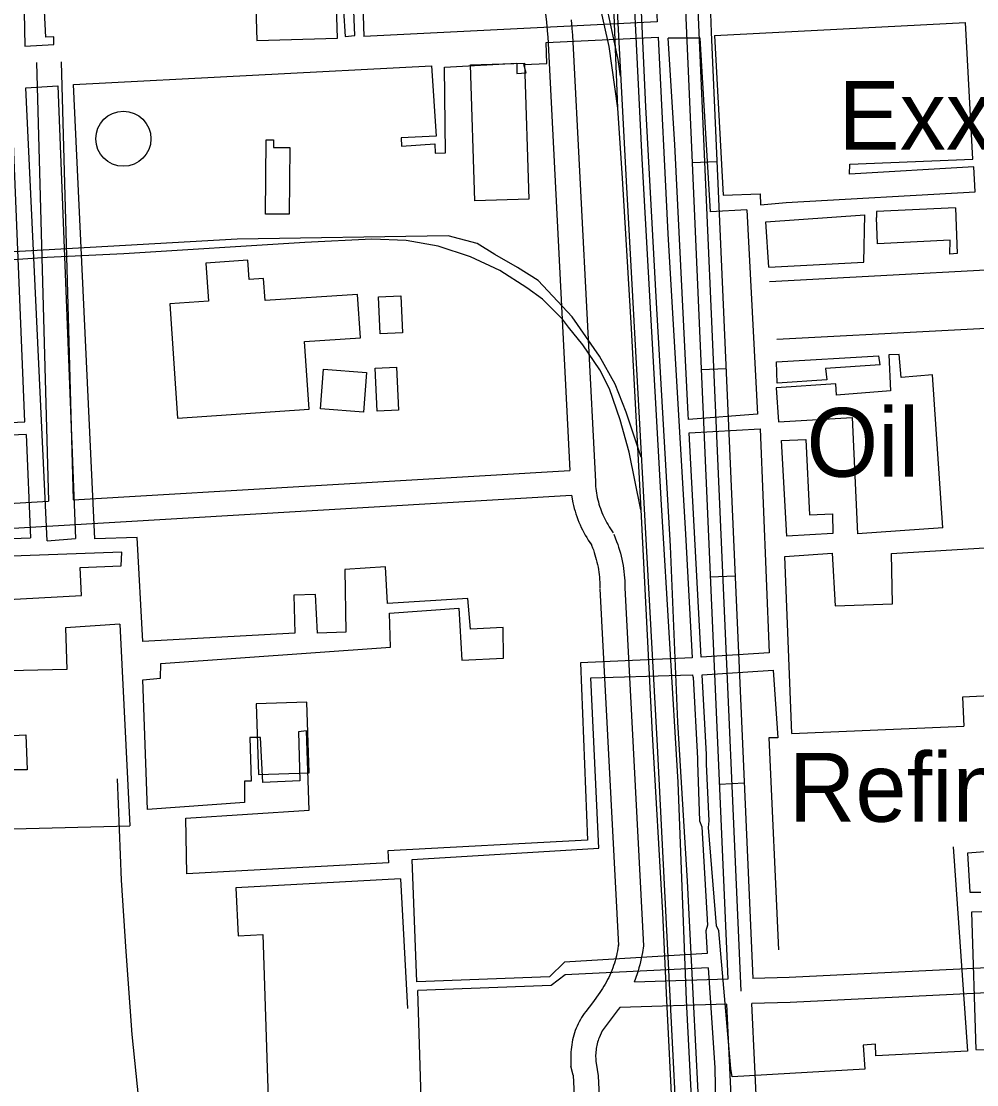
# Model space of a CAD drawing. Extents: x 3313447 to 3351316, y 703786 to 729172.
# Drawn here: x 3329508 to 3330659, y 721489 to 722771 of the extents above; entities that cross this region are included whole.
import ezdxf

# ---------------------------------------------------------------- set-up
doc = ezdxf.new("R2010")
doc.units = 0
for name, color, linetype in [('V-BLDG-IDEN', 7, 'Continuous'), ('V-BLDG-OTLN', 7, 'Continuous'), ('V-DOMW-TANK', 7, 'Continuous'), ('V-RAIL-TRAK', 7, 'Continuous'), ('V-ROAD-CNTR', 7, 'Continuous'), ('V-UTIL-LINE', 7, 'Continuous')]:
    doc.layers.add(name, color=color, linetype=linetype)

msp = doc.modelspace()

# ---------------------------------------------------------------- linework, layer by layer
at = {"layer": 'V-BLDG-OTLN'}
for points in [[(3330113.9, 722720.9), (3330119.2, 722556.9), (3330054.2, 722554.8), (3330048.9, 722718.8)], [(3329831.4, 722619.1), (3329830.7, 722538.7), (3329801.9, 722538.9), (3329802.7, 722628.4), (3329811.9, 722628.3), (3329811.9, 722619.2)], [(3329696.2, 722293), (3329854.5, 722303.6), (3329849, 722385.3), (3329916.4, 722389.8), (3329912.9, 722442), (3329801.6, 722434.5), (3329799.8, 722461.2), (3329782.6, 722460.1), (3329781, 722483.1), (3329730.4, 722479.7), (3329733.5, 722434), (3329687, 722430.8)], [(3329940.3, 722394.6), (3329938.3, 722439), (3329965.3, 722440.2), (3329967.3, 722395.8)], [(3329920.3, 722300.2), (3329868.5, 722303.9), (3329872, 722351.7), (3329923.7, 722348)], [(3329959.7, 722354.2), (3329962.3, 722302.5), (3329936.7, 722301.2), (3329934.1, 722352.9)], [(3329854.6, 721865.3), (3329851.9, 721950.4), (3329791, 721948.5), (3329793.7, 721863.3)]]:
    msp.add_lwpolyline(points, close=True, dxfattribs=at)
at = {"layer": 'V-DOMW-TANK'}
msp.add_circle((3329630.9, 722629.6), 33.2, dxfattribs=at)
at = {"layer": 'V-RAIL-TRAK'}
for points in [[(3330131.5, 724591.3), (3330139.3, 724420.3), (3330148.6, 724227.2), (3330159, 724024.7), (3330170.2, 723797.3), (3330181.3, 723583), (3330191.8, 723354.2), (3330204.1, 723119.5), (3330215.1, 722932.3), (3330219.8, 722830.3), (3330226.1, 722666.6)], [(3330326, 721424.9), (3330317.7, 721591.3), (3330310.5, 721734.5), (3330298.8, 721926.5), (3330289.8, 722138.4), (3330273, 722431.7), (3330260.4, 722668.1), (3330249.5, 722907), (3330231, 723213.3), (3330218.2, 723465.7), (3330204, 723743), (3330189.9, 724004.8), (3330176.5, 724253), (3330165.3, 724472.1), (3330161.1, 724586)], [(3330202.9, 722798.6), (3330215.6, 722740.7), (3330226.1, 722666.6), (3330231.7, 722582), (3330242.7, 722401), (3330254.2, 722182.2), (3330268, 721911.8), (3330280.2, 721696.5), (3330285.2, 721591.3), (3330291.8, 721453.8)], [(3330254.2, 722182.2), (3330240, 722251.9), (3330229.4, 722291), (3330216.3, 722328), (3330204.8, 722351.2), (3330184.5, 722381.3), (3330167.1, 722402.6), (3330159.7, 722412), (3330135.7, 722436.2), (3330116.9, 722450), (3330084.5, 722471), (3330049.1, 722487.4), (3330010.2, 722500.1), (3329971.6, 722506.8), (3329930, 722508.7), (3329849.6, 722504.5), (3329631.5, 722490.9), (3329538.9, 722486.4), (3329498, 722483.6), (3329390.2, 722477.2), (3329212, 722469), (3329084.7, 722462.8)]]:
    msp.add_lwpolyline(points, dxfattribs=at)
at = {"layer": 'V-ROAD-CNTR'}
for p, q in [((3330345.9, 722602), (3330315.9, 722600.7)), ((3330356.9, 722352.3), (3330326.9, 722351)), ((3330367.8, 722102.5), (3330337.9, 722101.2)), ((3330378.8, 721852.8), (3330348.8, 721851.4))]:
    msp.add_line(p, q, dxfattribs=at)
for points in [[(3330000.9, 727371.9), (3330011.6, 727012.1), (3330035.2, 726652.6), (3330064.9, 725878.2), (3330103.9, 725200.1), (3330125.1, 724765.2), (3330141.9, 724403.2), (3330158.8, 724097.3), (3330186.3, 723532.1), (3330236.4, 722578.7), (3330273.8, 721897.8), (3330314.5, 721094.9), (3330366.7, 720143), (3330425.8, 719049.4), (3330444.1, 718741)], [(3330466.9, 718738.2), (3330443.3, 719091.6), (3330425.1, 719389.4), (3330397.6, 719905.3), (3330375.8, 720281.9), (3330354.7, 720674.1), (3330332.4, 721137.8), (3330309.1, 721591.1), (3330299.2, 721854.1), (3330279.3, 722188.2), (3330255.7, 722605.3), (3330239.5, 722940.1), (3330206.8, 723536.2), (3330170.6, 724242), (3330145.9, 724754), (3330120.4, 725277), (3330081.8, 725930.6), (3330062.3, 726434.2), (3330049.6, 726666.1), (3330008.6, 727333.2), (3330005.4, 727371.9)], [(3330229.8, 722705), (3330226.8, 722725.1), (3330206.5, 722821.4), (3330186.6, 722875.1), (3330169.7, 722917.9), (3330137.7, 722976.9), (3330112.5, 723021.9), (3330083.6, 723061.2), (3330048.7, 723102.7), (3330000, 723151.4), (3329959.9, 723189.8), (3329906.5, 723223.6), (3329849.9, 723262.2), (3329775.5, 723299.1), (3329670.5, 723334.7), (3329586.2, 723351.8), (3329525.3, 723358.9), (3329412.1, 723359.9)], [(3330311.5, 723140.7), (3330302.4, 723128.7), (3330294.3, 723103.6), (3330309.1, 722757), (3330359.2, 721616.4)], [(3330309.4, 723101.6), (3330324, 722757.6), (3330374.8, 721601.9)], [(3330337.6, 722791.8), (3330339, 722758.3), (3330389.2, 721617.3)], [(3330139.3, 722780.4), (3330140.4, 722770.2), (3330141.3, 722760), (3330142, 722751.9)], [(3330170.2, 722773.1), (3330171.2, 722762.6), (3330171.9, 722754.5)], [(3330142, 722752.4), (3330168.8, 722229.7)], [(3330171.9, 722754), (3330199.5, 722216.4)], [(3329526.1, 722721.7), (3329540.5, 722192.6)], [(3329556.1, 722722.5), (3329570.5, 722194.4)], [(3330254.7, 722245.8), (3330236.7, 722300.1), (3330223.3, 722333.7), (3330204.4, 722367.5), (3330171.3, 722414.8), (3330130.4, 722458.7), (3330105.5, 722474.4), (3330078.5, 722490.1), (3330057.1, 722503.3), (3330022.3, 722512.8), (3329768, 722508.7), (3329300.1, 722482.1), (3329056.2, 722463.5)], [(3329570.5, 722194.4), (3330168.8, 722229.7)], [(3330199.5, 722216.2), (3330199.7, 722213.3), (3330199.8, 722210.6), (3330200.1, 722207.9), (3330200.4, 722205.2), (3330200.8, 722202.5), (3330201.3, 722199.8), (3330201.8, 722197.1), (3330202.4, 722194.5), (3330203.1, 722191.8), (3330203.8, 722189.2), (3330204.6, 722186.6), (3330205.5, 722184), (3330206.4, 722181.4), (3330207.4, 722178.9), (3330208.5, 722176.4), (3330209.6, 722173.9), (3330210.8, 722171.5), (3330212, 722169), (3330213.4, 722166.6), (3330214.7, 722164.3), (3330216.2, 722162), (3330220.9, 722154.7)], [(3328790.8, 722148.4), (3329540.5, 722192.6)], [(3329226.1, 722144), (3330170.7, 722199.8)], [(3330170.7, 722199.8), (3330172.4, 722190.9), (3330173.2, 722187.5), (3330174.1, 722184.1), (3330175, 722180.7), (3330176, 722177.4), (3330177.1, 722174.1), (3330178.3, 722170.8), (3330179.6, 722167.5), (3330181, 722164.3), (3330182.4, 722161.1), (3330184, 722158), (3330185.6, 722154.9), (3330187.3, 722151.8), (3330189, 722148.8), (3330190.9, 722145.8), (3330192.8, 722142.9), (3330194.7, 722140.1), (3330195, 722139.8)], [(3330221.8, 722152.9), (3330225.1, 722144.3), (3330226.4, 722140.7), (3330227.5, 722137.2), (3330228.6, 722133.6), (3330229.6, 722130), (3330230.6, 722126.3), (3330231.4, 722122.7), (3330232.1, 722119), (3330232.8, 722115.3), (3330233.4, 722111.6), (3330233.9, 722107.8), (3330234.3, 722104.1), (3330234.6, 722100.4), (3330234.8, 722096.6), (3330234.9, 722092.9), (3330235, 722089.2), (3330235, 722087.6)], [(3330193.4, 722142.5), (3330194.7, 722139.6), (3330195.9, 722136.7), (3330197, 722133.9), (3330198, 722131), (3330198.9, 722128.1), (3330199.8, 722125.2), (3330200.6, 722122.3), (3330201.4, 722119.3), (3330202.1, 722116.3), (3330202.7, 722113.3), (3330203.2, 722110.3), (3330203.7, 722107.3), (3330204.1, 722104.3), (3330204.4, 722101.3), (3330204.6, 722098.2), (3330204.8, 722095.2), (3330204.9, 722092.1), (3330205, 722089), (3330205, 722087.7)], [(3330205, 722086.9), (3330227.4, 721657.1)], [(3330234.9, 722088.4), (3330257.5, 721656.7)], [(3329623.3, 721857.9), (3329628.4, 721735.9), (3329634, 721650), (3329641, 721549.9), (3329650.8, 721455.7), (3329657, 721369.5), (3329664.8, 721286.5), (3329666.1, 721220.5), (3329668.7, 721162.2), (3329668.2, 721127.2), (3329562.6, 721122.8), (3329434.6, 721118.6), (3329349, 721114.9), (3329279.5, 721113)], [(3330227.5, 721659.9), (3330227.1, 721656.6), (3330226.6, 721653.6), (3330226.1, 721650.6), (3330225.5, 721647.6), (3330224.8, 721644.6), (3330224, 721641.7), (3330223.2, 721638.7), (3330222.3, 721635.8), (3330221.3, 721632.9), (3330220.3, 721630), (3330219.2, 721627.1), (3330218.1, 721624.3), (3330216.8, 721621.5), (3330215.5, 721618.7), (3330214.2, 721616), (3330212.8, 721613.3), (3330211.3, 721610.6), (3330209.7, 721608), (3330208.1, 721605.4), (3330206.5, 721602.8), (3330204.7, 721600.3), (3330195.8, 721587.9)], [(3330257.5, 721656.7), (3330256.2, 721648.7), (3330255.5, 721644.9), (3330254.8, 721641.3), (3330253.9, 721637.6), (3330253, 721633.9), (3330252, 721630.3), (3330250.9, 721626.7), (3330249.7, 721623.1), (3330246.1, 721613.1)], [(3331759.7, 721653.7), (3330434, 721588.6), (3330388, 721587.2)], [(3330836.1, 721638.4), (3330432.8, 721618.6), (3330389.2, 721617.3)], [(3330359.2, 721616.4), (3330246.4, 721613.1)], [(3330195.8, 721587.9), (3330187.8, 721577.6), (3330186.1, 721575.3), (3330184.5, 721572.8), (3330182.9, 721570.4), (3330181.4, 721567.8), (3330180, 721565.2), (3330178.7, 721562.6), (3330177.5, 721560), (3330176.3, 721557.3), (3330175.3, 721554.5), (3330174.3, 721551.7), (3330173.4, 721548.9), (3330172.7, 721546.1), (3330172, 721543.2), (3330171.4, 721540.4), (3330170.9, 721537.5), (3330170.5, 721534.6), (3330170.2, 721531.7), (3330169.9, 721528.7), (3330169.8, 721525.8), (3330169.7, 721511.6)], [(3330358, 721586.4), (3330228.9, 721582.5)], [(3330365.1, 721433.2), (3330358, 721586.4)], [(3330431.7, 720793.9), (3330395.1, 721434.7), (3330388, 721587.2)], [(3330228.9, 721582.5), (3330227.1, 721580), (3330207.6, 721554.2)], [(3330207.6, 721554.2), (3330204.1, 721546), (3330203.4, 721544.2), (3330202.8, 721542.4), (3330202.2, 721540.5), (3330201.7, 721538.6), (3330201.2, 721536.7), (3330200.9, 721534.8), (3330200.5, 721532.9), (3330200.3, 721530.9), (3330200, 721529), (3330199.9, 721527), (3330199.8, 721525.1), (3330199.8, 721523.1), (3330199.9, 721521.2), (3330200, 721519.2), (3330200.2, 721517.3), (3330200.4, 721515.3), (3330202.8, 721499.9)], [(3330172.7, 721500.9), (3330169.7, 721511.6)], [(3330172.7, 721500.9), (3330188.7, 721176.5)], [(3330202.8, 721499.9), (3330218.7, 721178)]]:
    msp.add_lwpolyline(points, dxfattribs=at)
at = {"layer": 'V-UTIL-LINE'}
for p, q in [((3330274, 722770.6), (3329920.4, 722752.8)), ((3330342.9, 722754.1), (3330645.4, 722769.6)), ((3330140, 722745.7), (3330275, 722752.3)), ((3330381.9, 722543.9), (3330394.6, 722297.5)), ((3330542.5, 722357.2), (3330541, 722367.9)), ((3330394.6, 722297.5), (3330311.7, 722291.2)), ((3329513.6, 722273), (3329519.1, 722148.7)), ((3330327, 722004.6), (3330312.5, 722275.3)), ((3330485.2, 722177.6), (3330485.3, 722153.7)), ((3330617.9, 722160.6), (3330515.1, 722153.5)), ((3329539.2, 722145), (3329573.1, 722147.6)), ((3329628.3, 722114.7), (3329628.9, 722131.3)), ((3329626.6, 722044.4), (3329638.6, 721801.4)), ((3330302, 721983.1), (3330316.9, 721983.5)), ((3330317.1, 721980.7), (3330316.9, 721983.5)), ((3330436.3, 721912.5), (3330643.3, 721921.5)), ((3329964.6, 721737.3), (3329973.1, 721581.3)), ((3330007.5, 720934), (3329985.4, 721602.8))]:
    msp.add_line(p, q, dxfattribs=at)
for points in [[(3330184.7, 724503.2), (3330185.3, 724490.2), (3330191.3, 724387.6), (3330230.5, 724261.8), (3330234.7, 724258.4), (3330237.5, 724237.1), (3330199.2, 724194.9), (3330218, 723872.7), (3330240.2, 723443.9), (3330270, 722851.2), (3330274, 722770.6)], [(3329912.1, 723021.8), (3329920.4, 722752.8)], [(3329894.1, 722816), (3329897.9, 722753), (3329909.7, 722754.1), (3329899, 723020.7)], [(3329785.8, 722947), (3329791.7, 722748), (3329888.9, 722750.9), (3329887.7, 722789)], [(3329511.4, 722782.2), (3329512, 722741.4), (3329547.3, 722743.3), (3329547.2, 722752.7), (3329537.5, 722752.3), (3329536, 722783.4)], [(3330342.9, 722754.1), (3330353.2, 722561.5), (3330398.1, 722563.4), (3330398.2, 722549.8), (3330429.1, 722552.8), (3330656.8, 722565.6), (3330655.4, 722595.6), (3330505.7, 722586.8), (3330505.9, 722599), (3330654.2, 722604.9), (3330645.4, 722769.6)], [(3330275, 722752.3), (3330286.8, 722515.2), (3330307.9, 722153.1), (3330315.9, 722003.7)], [(3330315.9, 722003.7), (3330181.5, 721997.7), (3330190.1, 721784.2), (3329949.6, 721771.2), (3329950.4, 721756.7), (3329707.4, 721743.7), (3329706, 721810.5), (3329854.5, 721820.2), (3329851.6, 721915.8), (3329841.9, 721914.7), (3329843.6, 721855.8), (3329798.9, 721853.5), (3329796.2, 721907.9), (3329783.4, 721907.8), (3329784.7, 721855.2), (3329776.8, 721855.1), (3329776.9, 721829.5), (3329659.9, 721821), (3329654.3, 721977.4), (3329675.7, 721979.3), (3329676, 721996.9), (3329952.5, 722016.7), (3329951.3, 722057.9), (3330035, 722063.8), (3330038.5, 722001.2), (3330088.6, 722003.5), (3330088.5, 722040.5), (3330049, 722038.6), (3330046, 722075.3), (3329949.1, 722069.3), (3329946.8, 722113.6), (3329897.7, 722110.2), (3329898.8, 722034.7), (3329864.8, 722033.5), (3329862.5, 722080.3), (3329836.2, 722079.4), (3329837.5, 722033.7), (3329654.4, 722023.5), (3329647.5, 722148.8), (3329596.7, 722147.5), (3329571, 722695), (3330002, 722717.6), (3330007.6, 722632.8), (3329965.7, 722630.9), (3329966.1, 722620.9), (3330006.2, 722623.5), (3330006.3, 722612.4), (3330019.1, 722612.8), (3330017.9, 722716), (3330104.8, 722720.6), (3330104.8, 722708.5), (3330115.9, 722709.2), (3330113.4, 722719.2), (3330141.1, 722720.4), (3330140, 722745.7)], [(3330381.9, 722543.9), (3330338, 722541.6), (3330325.8, 722751), (3330287.1, 722750.9)], [(3330311.7, 722291.2), (3330311.3, 722297.8), (3330295.2, 722622.7), (3330287.1, 722750.9)], [(3329539.2, 722145), (3329513.3, 722691.2), (3329552, 722693.5), (3329573.1, 722147.6)], [(3329476.9, 722286.7), (3329512.2, 722288.2), (3329496, 722682.8)], [(3330408.3, 722474.9), (3330404.8, 722529.6), (3330523.9, 722537.8)], [(3330408.3, 722474.9), (3330522.8, 722481), (3330523.9, 722537.8)], [(3330633.3, 722546.3), (3330538.1, 722542), (3330538.1, 722534.8)], [(3330633.3, 722546.3), (3330635.3, 722491.3), (3330626.6, 722490.5), (3330626.9, 722507.5), (3330539.3, 722502.9), (3330538.1, 722534.8)], [(3330418, 722388.1), (3330815.4, 722408.8), (3330811.2, 722479), (3330409.4, 722457.3)], [(3330617.9, 722160.6), (3330605.5, 722345), (3330567.8, 722341.7), (3330565.3, 722369.4), (3330553.1, 722369), (3330555.1, 722325.7), (3330490, 722320.6), (3330489.3, 722334.4), (3330417.3, 722329.5), (3330419.9, 722288.4), (3330508.9, 722293.7), (3330515.1, 722153.5)], [(3330542.5, 722357.2), (3330476.7, 722352.7), (3330478.2, 722338.9), (3330418.6, 722335.1), (3330417.5, 722360.7), (3330541, 722367.9)], [(3330312.5, 722275.3), (3330398.1, 722279.9), (3330408.8, 722009.9), (3330327, 722004.6)], [(3329513.6, 722273), (3329476.2, 722271.4), (3329478.2, 722225.4), (3329463.7, 722223.6), (3329460, 722269.3), (3329312.2, 722261.2), (3329313.3, 722241.2), (3329250, 722236.7), (3329250.8, 722139.1), (3329519.1, 722148.7)], [(3330485.3, 722153.7), (3330429.9, 722150.6), (3330423.8, 722265.9), (3330452.9, 722267.1), (3330457.2, 722176.4), (3330485.2, 722177.6)], [(3330436.3, 721912.5), (3330427.6, 722126), (3330484.8, 722130.1), (3330488.2, 722066.4), (3330557.4, 722068.9), (3330556.1, 722129.8), (3330780.7, 722143.4)], [(3329628.9, 722131.3), (3329253.4, 722117.6), (3329257.6, 722025.9), (3329328.9, 722028.3), (3329328.8, 722062.3), (3329309.4, 722061.8), (3329307.9, 722077.4), (3329368.8, 722079.4), (3329367.7, 722106.4), (3329390.9, 722108.3), (3329393.4, 722076.4), (3329446.7, 722078.4), (3329444.9, 722108.5), (3329475.3, 722109.7), (3329477.2, 722073.4), (3329580.4, 722079.1), (3329578.8, 722112.7), (3329628.3, 722114.7)], [(3329626.6, 722044.4), (3329561.2, 722040.2), (3329562.8, 721989.7), (3329370.4, 721985.3), (3329368, 722046.9), (3329343.7, 722046.4), (3329345.6, 722020.1), (3329259.1, 722016.2), (3329268.9, 721788.1), (3329391.1, 721794.6), (3329388.4, 721843.8), (3329358.3, 721841.5), (3329359.1, 721817.7), (3329323.1, 721813.3), (3329322.5, 721861.8), (3329350.9, 721864.3), (3329349.7, 721903.1), (3329513.4, 721911.2), (3329515, 721869), (3329493.8, 721868.9), (3329498, 721797.9), (3329638.6, 721801.4)], [(3330334.2, 721647.5), (3330162.1, 721636.9), (3330144.2, 721619.5), (3329984.3, 721613.5), (3329978.7, 721760.9), (3330203.7, 721774.5), (3330194, 721979.8), (3330302, 721983.1)], [(3330328.1, 721983.5), (3330413.8, 721988.9), (3330419.1, 721907.5), (3330408.3, 721907.5), (3330420, 721651.7)], [(3330362.8, 721508.9), (3330348.2, 721674.8), (3330345.4, 721681), (3330335.9, 721799.4), (3330336.5, 721807.6), (3330333.4, 721875.8), (3330333.4, 721887.5), (3330328.1, 721983.5)], [(3330317.1, 721980.7), (3330322.4, 721882.6), (3330322.4, 721877.8), (3330324.8, 721807.6), (3330327.6, 721800), (3330334.4, 721681.6), (3330332.4, 721674.7), (3330334.2, 721647.5)], [(3330675.3, 721958), (3330641.8, 721956.4), (3330643.3, 721921.5)], [(3330630.5, 721776), (3330647.7, 721529.6), (3330537.2, 721524.2), (3330536.9, 721538.2), (3330522.2, 721537), (3330524, 721508.2)], [(3330694.2, 721772.1), (3330647.9, 721768.4), (3330650.7, 721721.6), (3330663.8, 721721.6)], [(3329964.6, 721737.3), (3329766.2, 721726.5), (3329769.3, 721668.9), (3329798.8, 721670.5), (3329812.3, 721261.9)], [(3330665.1, 721697.8), (3330652.7, 721697.2), (3330657.7, 721531.8), (3330679.4, 721531.2)], [(3330335.4, 721630.2), (3330163.2, 721621.8), (3330146.2, 721608.8), (3329985.4, 721602.8)], [(3330335.4, 721630.2), (3330343.5, 721509.5), (3330344.6, 721442.7), (3330365.2, 721042.8), (3330376.2, 720875.6)], [(3330524, 721508.2), (3330364.2, 721498.7), (3330362.8, 721508.9)]]:
    msp.add_lwpolyline(points, dxfattribs=at)

# ---------------------------------------------------------------- texts
at = {"layer": 'V-BLDG-IDEN'}
for s, p in [('Exxon', (3330492.1, 722616.4)), ('Oil', (3330453.8, 722222.2)), ('Refining Co.', (3330432.4, 721806.3))]:
    msp.add_text(s, height=83, dxfattribs=at).set_placement(p)

doc.saveas('drawing.dxf')
